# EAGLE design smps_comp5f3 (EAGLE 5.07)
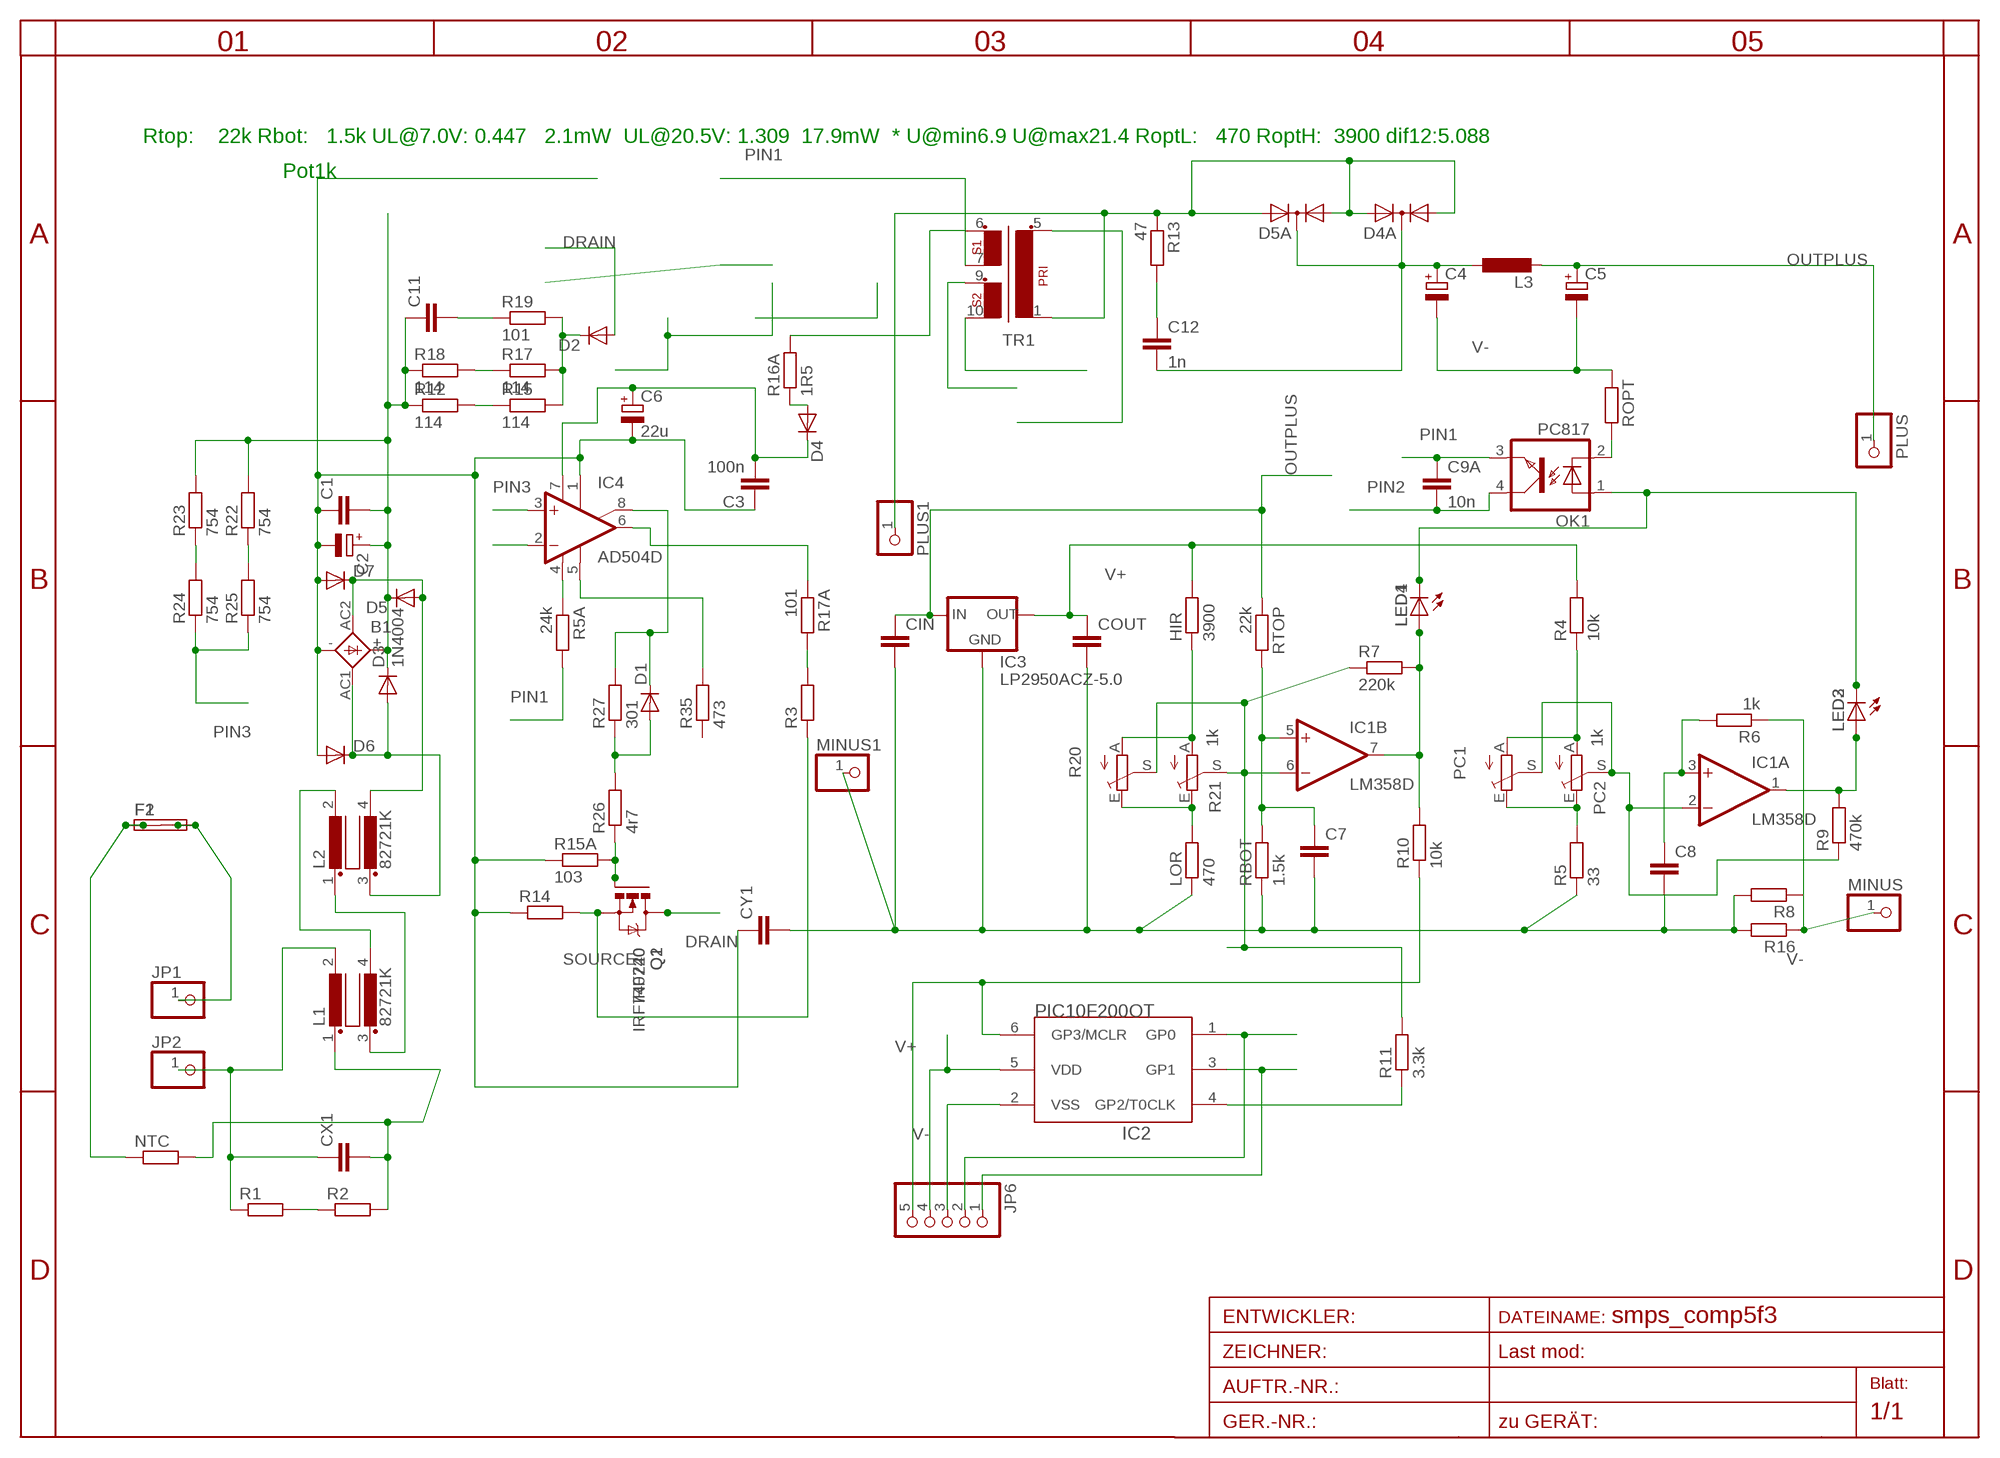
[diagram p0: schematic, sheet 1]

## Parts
B1  KBL  [KBL]
C1  C-EU050-024X044  [C050-024X044]
C2  CPOL-EUE7.5-16  [E7,5-16]
C3  100n  C-EUC0805  [C0805]
C4  CPOL-EUE5-8.5  [E5-8,5]
C5  CPOL-EUE5-8.5  [E5-8,5]
C6  22u  CPOL-EUE2.5-6  [E2,5-6]
C7  C-EUC0805  [C0805]
C8  C-EUC0805  [C0805]
C9A  10n  C-EUC0805  [C0805]
C11  C-EUC1206  [C1206]
C12  1n  C-EUC1206  [C1206]
CIN  C-EUC1206  [C1206]
COUT  C-EUC1206  [C1206]
CX1  C-EU150-084X183  [C150-084X183]
CY1  C-EU075-063X106  [C075-063X106]
D1  DIODE-MINIMELF  [MINIMELF]
D2  DIODE-C1702-15  [C1702-15]
D3  1N4004  [DO41-10]
D4  DIODE-MINIMELF  [MINIMELF]
D4A  DIODE-2AC|CAIW220V  [IW220ABS]
D5  DIODE-D-5  [D-5]
D5A  DIODE-2AC|CAIW220V  [IW220ABS]
D6  DIODE-D-5  [D-5]
D7  DIODE-D-7.5  [D-7.5]
F1  SHK20L20MM  [SHK20L]
F2  SHK20L7MM5  [7MM5]
HIR  3900  R-EU_R0805  [R0805]
IC1  LM358D  [SO08]
IC2  PIC10F200OT  [SOT23-6]
IC3  LP2950ACZ-5.0  [TO92]
IC4  AD504D  [SO08]
JP1  PINHD-1X12MM2  [1X2MM2]
JP2  PINHD-1X12MM2  [1X2MM2]
JP6  PINHD-1X5/90  [1X05/90]
L1  82721K  82721K7_5X10  [8272_7.5_10]
L2  82721K  82721K7_5  [8272_7.5]
L3  L-EU0207/12  [0207/12]
LED1  LED3MM  [LED3MM]
LED2  LED3MM  [LED3MM]
LED3  LEDCHIPLED_1206  [CHIPLED_1206]
LED4  LEDCHIPLED_1206  [CHIPLED_1206]
LOR  470  R-EU_R0805  [R0805]
MINUS  PINHD-1X12MM2  [1X2MM2]
MINUS1  PINHD-1X11X0.4  [1X01]
NTC  R-EU_0204/7  [0204/7]
OK1  PC817  [DIL04]
PC1  TRIM_EU-S64W  [S64W]
PC2  1k  TRIM_EU-CA6V  [CA6V]
PLUS  PINHD-1X12MM2  [1X2MM2]
PLUS1  PINHD-1X11X0.4  [1X01]
Q1  IRF740  IRF740X  [TO220VX]
Q2  IRF740220  [TO220BV]
R1  R-EU_R1206  [R1206]
R2  R-EU_R1206  [R1206]
R3  R-EU_0207/40  [0207/40]
R4  10k  R-EU_R0805  [R0805]
R5  33  R-EU_R1206  [R1206]
R5A  24k  R-EU_R0805  [R0805]
R6  1k  R-EU_R0805  [R0805]
R7  220k  R-EU_R0805  [R0805]
R8  R-EU_R2010  [R2010]
R9  470k  R-EU_R0805  [R0805]
R10  10k  R-EU_0207/15  [0207/15]
R11  3.3k  R-EU_0207/15  [0207/15]
R12  114  R-EU_R1206  [R1206]
R13  47  R-EU_R1206  [R1206]
R14  R-EU_0411/3V  [0411V]
R15  114  R-EU_R1206  [R1206]
R15A  103  R-EU_R1206  [R1206]
R16  R-EU_R2010  [R2010]
R16A  1R5  R-EU_R1206  [R1206]
R17  114  R-EU_R1206  [R1206]
R17A  101  R-EU_R0805  [R0805]
R18  114  R-EU_R1206  [R1206]
R19  101  R-EU_R1206  [R1206]
R20  TRIM_EU-S64W  [S64W]
R21  1k  TRIM_EU-CA6V  [CA6V]
R22  754  R-EU_R1206  [R1206]
R23  754  R-EU_R1206  [R1206]
R24  754  R-EU_R1206  [R1206]
R25  754  R-EU_R1206  [R1206]
R26  4r7  R-EU_R1206  [R1206]
R27  301  R-EU_R1206  [R1206]
R35  473  R-EU_R1206  [R1206]
RBOT  1.5k  R-EU_R0805  [R0805]
ROPT  R-EU_R0805  [R0805]
RTOP  22k  R-EU_R0805  [R0805]
TR1  EE20-2  [EE30GREEN]

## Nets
A: PC1.A PC2.A R4.1
A1: HIR.1 R20.A R21.A
AC1: F1.2A F1.2B F2.2A F2.2B JP1.1
AC2: CX1.1 JP2.1 L1.2 R1.1
CPLUS: C4.+ C12.2 D4A.C D5A.C L3.1
DRAIN: D2.A Q1.D Q2.D TR1.10
E: PC1.E PC2.E R5.2
E1: LOR.2 R20.E R21.E
F1A: F1.1A F1.1B F2.1A F2.1B NTC.1
GATE: Q1.G Q2.G R15A.2 R26.1
N$1: CX1.2 L1.1 NTC.2 R2.2
N$3: L1.4 L2.2
N$4: B1.AC1(AC2) D3.A D6.C L2.3
N$5: L1.3 L2.1
N$6: R1.2 R2.1
N$7: C8.1 IC1.3(A:+IN) R6.2
N$10: IC1.6(B:-IN) R7.1 R11.2 R20.S R21.S
N$11: IC1.1(A:OUT) LED2.A LED3.A R9.2
N$12: OK1.2(C) ROPT.2
N$13: LED1.K(C) LED2.K(C) LED3.C LED4.C OK1.1(A)
N$15: IC2.6(GP3/MCLR) JP6.5 R10.1
N$16: C7.1 IC1.5(B:+IN) RBOT.2 RTOP.2
N$17: IC2.1(GP0) JP6.2
N$18: IC2.3(GP1) JP6.1
N$19: IC2.4(GP2/T0CLK) R11.1
N$20: B1.AC2(AC1) D5.A D7.C L2.4
N$23: C11.2 R19.1
N$24: D2.C R15.2 R17.2 R19.2
N$25: D1.A R26.2 R27.1
N$26: R17.1 R18.2
N$27: C12.1 R13.2
N$28: R12.2 R15.1
N$29: R22.1 R25.2
N$30: IC4.4(V-) R5A.1
N$31: R23.1 R24.2
N$32: IC4.6(OUT) R17A.1
N$33: D1.C IC4.8(ON2) R27.2
N$34: R3.2 R17A.2
OUT: MINUS.1 R6.1 R8.1 R16.1
OUTB: IC1.7(B:OUT) LED1.A LED4.A R7.2 R10.2
OUTPLUS: C5.+ CIN.1 IC3.3(IN) L3.2 PLUS.1 RTOP.1
PIN1: B1.- C1.1 C2.- C3.1 C6.- C9A.1 CY1.1 D6.A D7.A IC4.1(ON1) OK1.3(EMIT) R5A.2 R14.1 R15A.1 TR1.9
PIN2: C9A.2 IC4.2(-IN) OK1.4(COL)
PIN3: IC4.3(+IN) R24.1 R25.1
PIN5: IC4.5(OPT) R35.2
PIN7: C3.2 C6.+ D4.C IC4.7(V+)
PLUS: B1.+ C1.2 C2.+ C11.1 D3.C D5.C R12.1 R18.1 R22.2 R23.2 TR1.7
S: IC1.2(A:-IN) PC1.S PC2.S R9.1
SOURCE: Q1.S Q2.S R3.1 R14.2
TPLUS: D4A.A1 D4A.A2 D5A.A1 D5A.A2 PLUS1.1 R13.1 TR1.1
V+: COUT.1 HIR.2 IC2.5(VDD) IC3.1(OUT) JP6.4 R4.2
V-: C4.- C5.- C7.2 C8.2 CIN.2 COUT.2 CY1.2 IC2.2(VSS) IC3.2(GND) JP6.3 LOR.1 MINUS1.1 R5.1 R8.2 R16.2 RBOT.1 ROPT.1 TR1.5
X: R16A.2 TR1.6
Y: D4.A R16A.1
Unconnected: R35.1

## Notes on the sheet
- Rtop:    22k Rbot:   1.5k UL@7.0V: 0.447   2.1mW  UL@20.5V: 1.309  17.9mW  * U@min6.9 U@max21.4 RoptL:   470 RoptH:  3900 dif12:5.088
- Pot1k

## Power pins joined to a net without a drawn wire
V+: IC1.8(P:V+)
V-: IC1.4(P:V-)

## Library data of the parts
B1 = rectifier:KBL: DIOTEC RECTIFIER
C1 C3 C7 C8 C9A C11 C12 CIN COUT CX1 CY1 = rcl:C-EU: CAPACITOR, European symbol
C2 C4-C6 = rcl:CPOL-EU: POLARIZED CAPACITOR, European symbol
D1 D2 D4-D7 = diode:DIODE-: DIODE
D3 = diode:1N4004: DIODE
D4A D5A = diode:DIODE-2AC|CA: Dual DIODE Anode-Cathode|Cathode-Anode
F1 F2 = fuse:SHK20L: FUSE HOLDER 5 x 20 mm, SH contact, SHH1 Schukat, E1073 Buerklin
HIR LOR NTC R1 R2 R4 R5 R5A R6-R15 R15A R16 R16A R17 R17A R18 R19 R22-R27 R35 RBOT ROPT RTOP = rcl:R-EU_: RESISTOR, European symbol
IC1 = linear:LM358: OP AMP also LM158; LM258; LM2904 Source: http://cache.national.com/ds/LM/LM158.pdf
IC2 = microchip-5:PIC10F20*: uPC nW 0,25/0,5k Program Flash memory
IC3 = v-reg:LP2950?*: Source: http://cache.national.com/ds/LP/LP2950.pdf
IC4 = linear:AD504: OP AMP
JP1 JP2 MINUS MINUS1 PLUS PLUS1 = pinhead:PINHD-1X1: PIN HEADER
JP6 = pinhead:PINHD-1X5: PIN HEADER
L1 L2 = inductors:82721K: FILTER
L3 = rcl:L-EU: INDUCTOR, European symbol
LED1-LED4 = led:LED: LED
OK1 = optocoupler:PC817: SHARP OPTO COUPLER
PC1 PC2 R20 R21 = pot:TRIM_EU-: POTENTIOMETER
Q1 Q2 = transistor-power:IRF740: N-CHANNEL MOS FET
R3 = rcl-2:R-EU_: RESISTOR, European symbol
TR1 = trafo:EE20-2: TRANSFORMER 1 primary winding, 2 secondary windings ERA

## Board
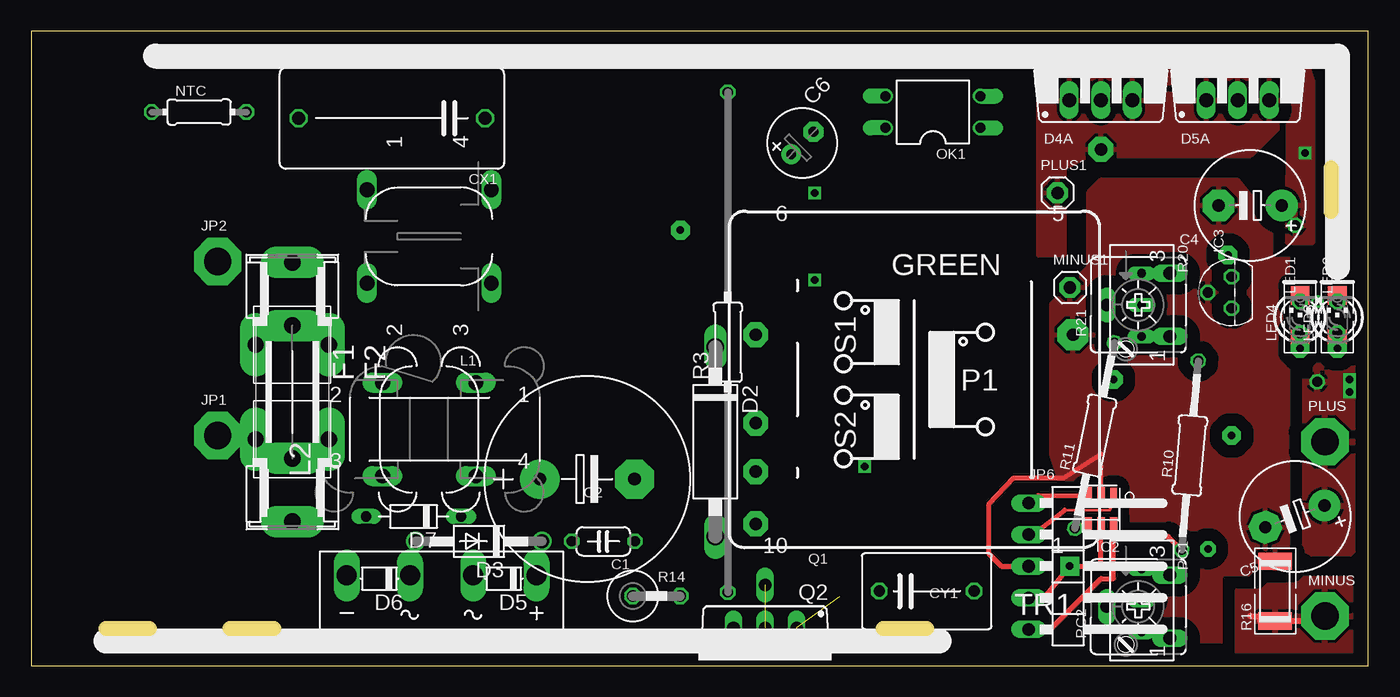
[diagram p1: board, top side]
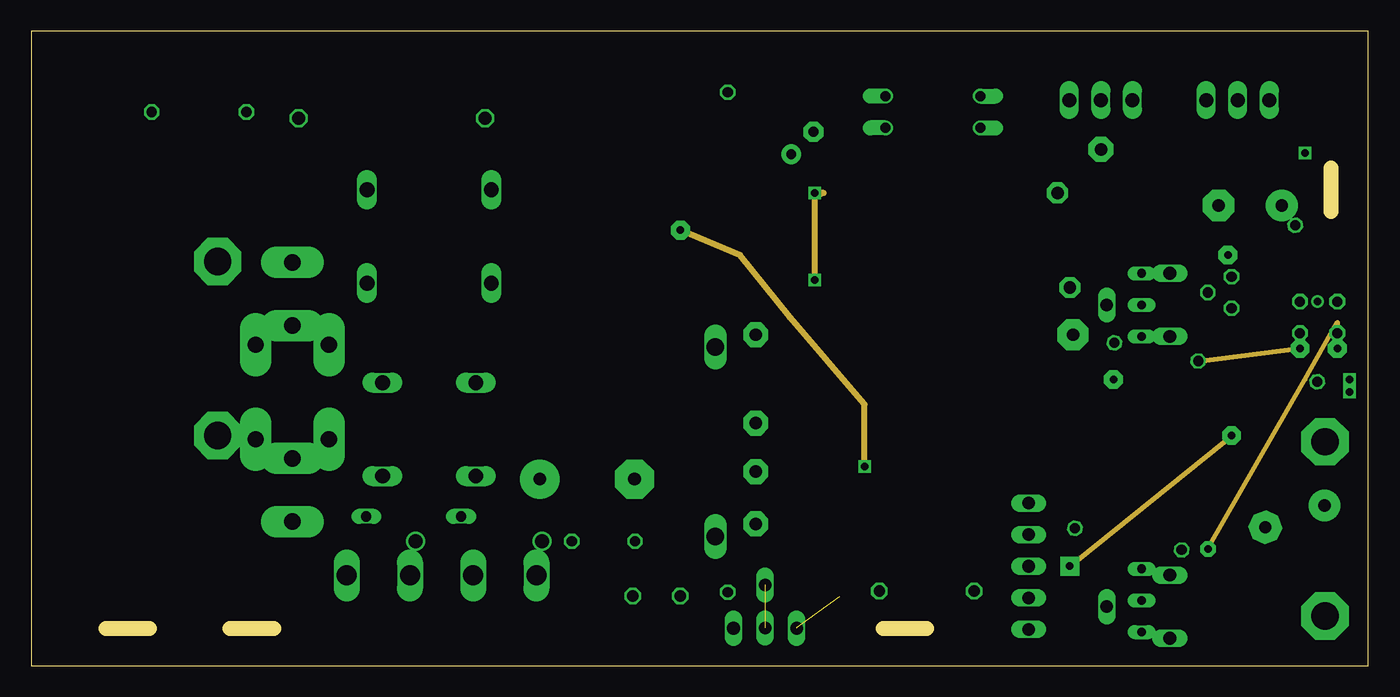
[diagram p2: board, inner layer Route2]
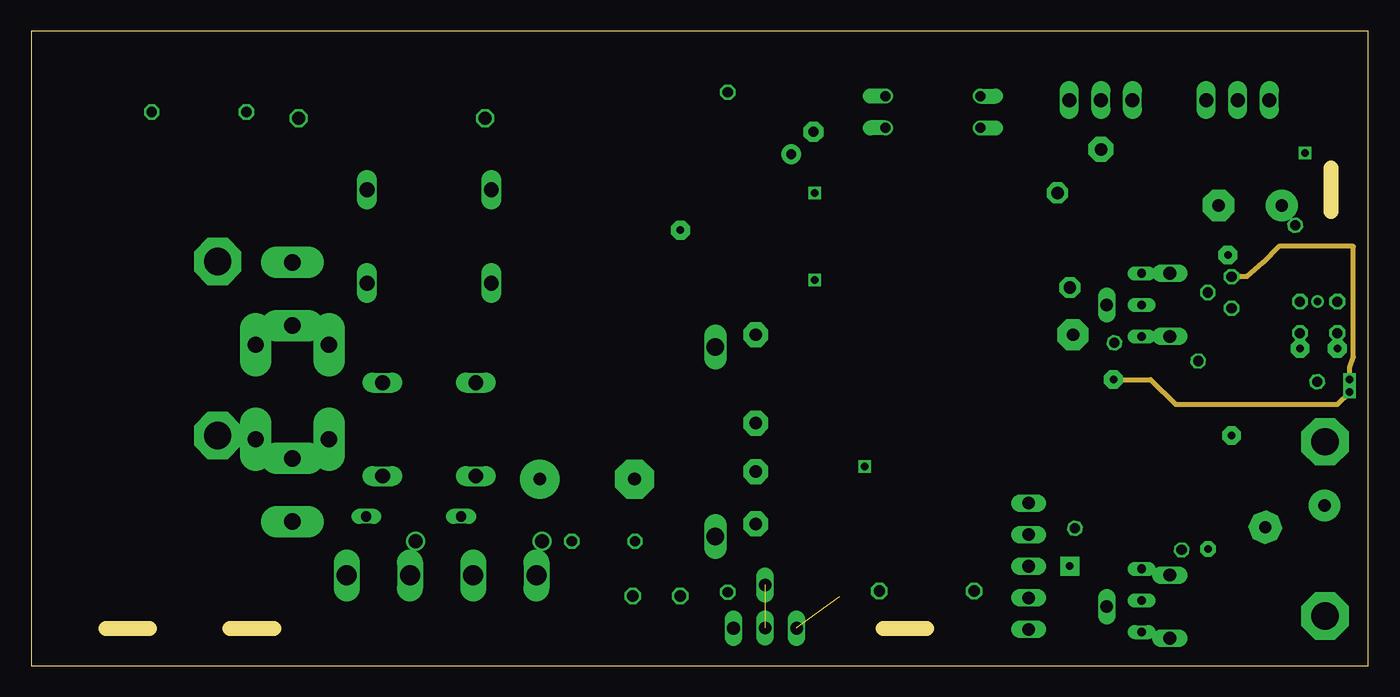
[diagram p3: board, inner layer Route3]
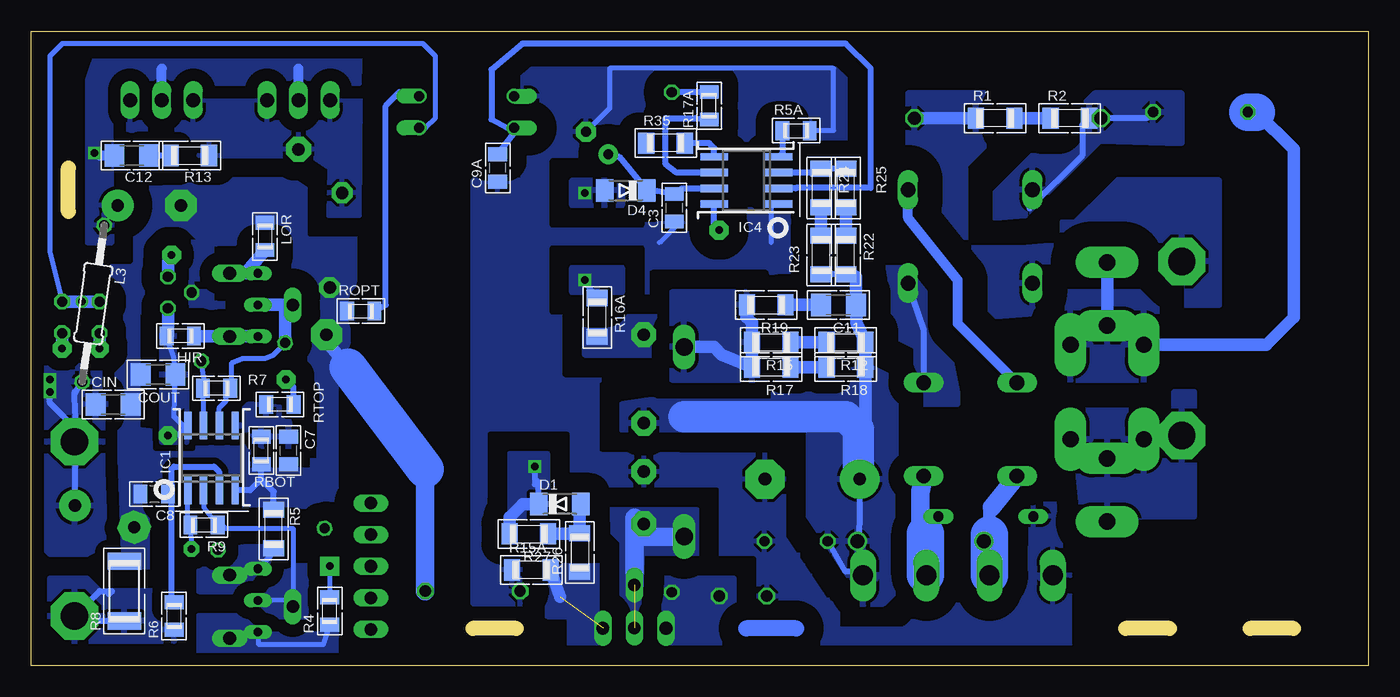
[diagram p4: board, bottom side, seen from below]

Size 107.5 x 51 mm. Coordinates in mm from the lower left corner, seen from the top.
Outline: 0,0 107.5,0 107.5,51 0,51 0,0
Copper layers (1*16): Top 0.035mm / dielectric 1.5mm / Bottom 0.035mm
Design rules "default *": minimum track width 10mil, minimum drill 20mil, track to track 8mil, track to pad 8mil, pad to pad 8mil, via to via 8mil, smd to smd 8mil, copper to edge 40mil, drill to drill 8mil, minimum pad ring 8mil, minimum via ring 8mil, stop-mask expansion 4mil, vias tented up to drill 0mil, thermal gap 10mil
Milling: 4 lines

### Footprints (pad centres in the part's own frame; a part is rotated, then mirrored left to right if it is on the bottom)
KBL = drill 1.6 long: + -7.62,-1.27; - 7.62,-1.27; AC1 2.54,-1.27; AC2 -2.54,-1.27
C050-024X044 = drill 0.813 octagon: 1 -2.54,0; 2 2.54,0
E7,5-16 = drill 1.016 pad 3.15 round: + -3.81,0 | drill 1.016 pad 3.15 octagon: - 3.81,0
C0805 = smd 1.1 x 1.5: 1 -1.1,0; 2 1.1,0
E5-8,5 = drill 1 pad 2.54 round: + -2.54,0 | drill 1 pad 2.54 octagon: - 2.54,0
E2,5-6 = drill 0.8 pad 1.6 round: + -1.27,0 | drill 0.8 pad 1.6 octagon: - 1.27,0
C1206 = smd 1.6 x 1.8: 1 -1.4,0; 2 1.4,0
C150-084X183 = drill 1.016 octagon: 1 -7.493,0; 2 7.493,0
C075-063X106 = drill 0.914 octagon: 1 -3.81,0; 2 3.81,0
MINIMELF = smd 1.4 x 1.8: A 1.7,0; C -1.7,0
C1702-15 = drill 1.397 long: A 7.62,0; C -7.62,0
DO41-10 = drill 1.118 round: A 5.08,0; C -5.08,0
IW220ABS = drill 1.118 long: A1 -2.54,-2.54; A2 2.54,-2.54; C 0,-2.54
D-5 = drill 0.813 octagon: A 2.54,0; C -2.54,0
D-7.5 = drill 0.813 long: A 3.81,0; C -3.81,0
SHK20L = drill 1.321 pad 2.54 long: 1A -10.414,0; 1B -5.334,0; 2A 10.414,0; 2B 5.334,0
7MM5 = drill 1.3 pad 2.54 long: 1A -3.8,2.94; 1B -3.8,-2.94; 2A 3.8,2.94; 2B 3.8,-2.94
R0805 = smd 1.1 x 1.5: 1 -1.1,0; 2 1.1,0
SO08 = smd 0.6 x 2.2: 1 -1.905,-2.6; 2 -0.635,-2.6; 3 0.635,-2.6; 4 1.905,-2.6; 5 1.905,2.6; 6 0.635,2.6; 7 -0.635,2.6; 8 -1.905,2.6
SOT23-6 = smd 0.55 x 1.2: 1 -1.016,-1.2 | smd 0.6 x 1.27: 2 0,-1.2; 3 1.016,-1.2; 4 1.016,1.2; 5 0,1.2; 6 -1.016,1.2
TO92 = drill 0.813 octagon: 1 -1.27,0; 2 0,1.905; 3 1.27,0
1X2MM2 = drill 2.2 pad 3.81 octagon: 1 0,0
1X05/90 = drill 1.016 long: 1 -5.08,-3.81; 2 -2.54,-3.81; 3 0,-3.81; 4 2.54,-3.81; 5 5.08,-3.81
8272_7.5_10 = drill 1.194 long: 1 3.75,5; 2 -3.75,5; 3 -3.75,-5; 4 3.75,-5
8272_7.5 = drill 1.194 long: 1 3.75,3.75; 2 -3.75,3.75; 3 -3.75,-3.75; 4 3.75,-3.75
0207/12 = drill 0.813 octagon: 1 -6.35,0; 2 6.35,0
LED3MM = drill 0.8 pad 1.27 octagon: A -1.27,0; K 1.27,0
CHIPLED_1206 = smd 1.5 x 1.5: A 0,-1.75; C 0,1.75
1X01 = drill 1 pad 1.676 octagon: 1 0,0
0204/7 = drill 0.813 octagon: 1 -3.81,0; 2 3.81,0
DIL04 = drill 0.813 offset: 1 -1.27,-3.81; 2 1.27,-3.81; 3 1.27,3.81; 4 -1.27,3.81
S64W = drill 0.7 long: A 2.54,1.27; E -2.54,1.27; S 0,1.27
CA6V = drill 1.016 long: A -2.54,-2.54; E 2.54,-2.54; S 0,2.54
TO220VX = drill 1.016 long: D 0,-3.5; G -2.54,0; S 2.54,0
TO220BV = drill 1.016 long: D 0,-2.54; G -2.54,-2.54; S 2.54,-2.54
R1206 = smd 1.3 x 1.7: 1 -1.55,0; 2 1.55,0
0207/40 = drill 0.813 octagon: 1 -20.08,0; 2 20.08,0
R2010 = smd 1.4 x 2.7: 1 -2.4,0; 2 2.4,0
0207/15 = drill 0.813 octagon: 1 -7.62,0; 2 7.62,0
0411V = drill 0.914 octagon: 1 -2.54,0; 2 1.27,0
EE30GREEN = drill 1 pad 2 octagon: 1 15,18.5; 6 -12.75,3.6; 7 -12.75,-3.5; 9 -12.75,-7.4; 10 -12.75,-11.6 | drill 1 pad 2.5 octagon: 5 12.75,3.6

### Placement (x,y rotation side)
B1  33,6 180 top
C1  46,10 180 top
C2  44.7,15 0 top
C3  55.8,36.8 90 bottom
C4  98,37 180 top
C5  101.6,12 200 top
C6  62,42 45 top
C7  86.8,17.3 270 bottom
C8  97.6,13.8 180 bottom
C9A  70,40 90 bottom
C11  42.6,29 180 bottom
C12  99.4,41 180 bottom
CIN  100.9,21 0 bottom
COUT  97.3,23.4 180 bottom
CX1  29,44 180 top
CY1  72,6 0 top
D1  65,13 0 bottom
D2  55,18 270 top
D3  36,10 180 top
D4  59.7,38.2 180 bottom
D4A  86,48 0 top
D5  38,7 180 top
D5A  97,48 0 top
D6  28,7 180 top
D7  30.75,12 180 top
F1  21,22 270 top
F2  21,22 270 top
HIR  95.5,26.5 180 bottom
IC1  93,16.7 0 bottom
IC2  86,12.5 180 top
IC3  96.5,30 90 top
IC4  50,39 90 bottom
JP1  15,18.5 0 top
JP2  15,32.5 0 top
JP6  84,8 270 top
L1  32,34.5 90 top
L2  32,19 0 top
L3  102.5,29.1 262 bottom
LED1  102,28 90 top
LED2  105,28 90 top
LED3  105,28 0 top
LED4  102,28 0 top
LOR  88.7,34.5 270 bottom
MINUS  104,4 0 top
MINUS1  83.5,30.4 0 top
NTC  13.5,44.5 0 top
OK1  72.5,44.5 90 top
PC1  88,5.25 270 top
PC2  89,4.75 90 top
PLUS  104,18 0 top
PLUS1  82.5,38 0 top
Q1  59,3 180 top
Q2  59,0.5 180 top
R1  30,44 0 bottom
R2  24,44 0 bottom
R3  56,26 90 top
R4  83.5,4.4 90 bottom
R5  88,11 270 bottom
R5A  46,43 0 bottom
R6  96,4 90 bottom
R7  92.6,22.3 180 bottom
R8  100,6 90 bottom
R9  93.6,11.3 180 bottom
R10  93.15,16.9 85 top
R11  85.5,18.5 78 top
R12  42,26 180 bottom
R13  94.75,41 180 bottom
R14  50.9,5.6 0 top
R15  48,26 180 bottom
R15A  67.3,7.7 0 bottom
R16  100,6 90 top
R16A  62,28 270 bottom
R17  48,24 180 bottom
R17A  53,45 90 bottom
R18  42,24 180 bottom
R19  48.4,29 180 bottom
R20  88,29 270 top
R21  89,29 90 top
R22  42,33 270 bottom
R23  44,33 270 bottom
R24  44,38.4 270 bottom
R25  42,38.4 270 bottom
R26  63.4,9.1 90 bottom
R27  67.5,10.6 180 bottom
R35  56.5,42 0 bottom
RBOT  89,17.3 90 bottom
ROPT  81,28.5 0 bottom
RTOP  87.5,21 180 bottom
TR1  71,23 0 top

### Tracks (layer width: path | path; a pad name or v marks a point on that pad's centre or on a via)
A
  Bottom 0.4: R4.1 84.01,1.7 89.2,1.7 89.2,2.71 PC1.A
  Bottom 0.5: PC1.A PC2.A
  pour Bottom (isolate 1, rank 2, no thermals): 83,4 94,4 94,1 83,1
A1
  Bottom 0.5: R21.A 92.46,26.5
  Bottom 1: R20.A R21.A | 92.46,26.5 HIR.1
AC1
  Bottom 0.5: F1.2B 22.41,16.67 F2.2A
  pour Bottom (isolate 2, rank 3): 14,22 24,22 23,12 14,12
AC2
  Bottom 1: R1.1 CX1.1
  pour Bottom (isolate 2, rank 3): 30,46 37,46 37,40 31,28 18,29 12,29 12,39 30,39
CPLUS  (via drill 0.6)
  Bottom 0.813: D4A.C 86,48 | D5A.C 97,48 | C12.2 102,41
  other vias: 102.4,41.2
  pour Bottom (isolate 1): 81,50 102,50 103,47 103,34 101,34 101,37 101.1,46.8 81.1,46.8
  pour Top (isolate 1): 81,50 102,50 103,47 103,34 101,34 101,37 101.1,46.8 81.1,46.8
DRAIN  (1 unrouted)
  Bottom 1.5: 59,11 Q1.D | 59,11 59,11.89 TR1.10 | D2.A 58.38,10.38 59,11
  pour Bottom (isolate 1.6, rank 2, no thermals): 54,12.5 61,12.5 61,11 60,10 60,3 58,3 58,8 54,8
E
  Bottom 0.406: R5.2 88.27,8.8 PC1.E PC2.E
  pour Bottom (isolate 1, rank 2, no thermals): 90,7 89,7 87,10 94,9 94,6 91,6
E1
  Bottom 0.406: 90.27,31.6 R20.E
  Bottom 1: R20.E R21.E | LOR.2 90.27,31.6
F1A
  Bottom 0.5: F1.1B 22.41,27.33
  Bottom 1: 9,44.5 6,41.5 6,28 8.2,25.8 F2.1B 19.59,27.33 F1.1B F1.1A | 22.41,27.33 F2.1A
  Bottom 3: 9,44.5 NTC.1
  pour Bottom (isolate 2): 17,26 17,30 25,30 25,23 17,23
GATE  (2 unrouted)
  Bottom 1: 64.99,5.54 R15A.2
  pour Bottom (isolate 1.6, rank 3, no thermals): 61,8 66,8 66,4 64.2,4 64.2,1 61,1
N$1
  Bottom 0.5: 21.51,43.74 CX1.2 17.81,44 NTC.2 | L1.1 27.25,36.75 23,41 23,43.45 R2.2
  Bottom 1: CX1.2 R2.2
  pour Bottom (isolate 2, rank 2): 15,46 22,46 30,38 30,36 27.6,36.2 21.6,42.2 15,42
N$2
  Bottom 1.27: 46,3 50,3
N$3
  Bottom 0.5: 36.75,37.75 L1.4
  Bottom 0.813: 36.75,37.75 37,37.75 37,36 33,31 33,27.5 L2.2
N$4
  Bottom 0.5: D6.C 30.54,7.19 B1.AC1 | 30.46,12.54 30.25,12.75
  Bottom 1: 30.46,10.54 30.46,12.54
  Bottom 1.5: 30.25,12.75 L2.3 | 30.46,10 D3.A
  Bottom 3: B1.AC1 30.46,10 30.46,10.54
N$5
  Bottom 0.5: L2.1 35.75,27 L1.3
  pour Bottom (isolate 2, rank 6, no thermals): 33,22 35,32 40,32 40,21 33,21
N$6
  Bottom 1: R2.1 R1.2
N$7
  Bottom 0.5: R6.2 96.2,5 96.2,14.65 | 96.2,14.65 C8.1 | 96.2,14.65 96.2,15.8 96,16 92.8,16 92.4,15.6 92.4,14.13 IC1.3
N$10
  Bottom 0.4: 91.36,24.34 90.5,24.7 88.7,24.7
  Bottom 0.406: 87.08,29 R21.S | R11.2 87.08,25.92 88,25 88.7,24.7 | IC1.6 92.36,20.73 91.8,21.3 91.8,22 R7.1 91.36,22.43 91.36,24.34
  Bottom 1: R21.S R20.S | R11.2 87.08,29
N$11  (via drill 0.6 pad 1.25, 0.6 pad 1.5)
  Top 0.5: v105,25.5 LED3.A
  Route2 0.406: v94.6,9.4 102.4,23 105,27.6 v105,25.5
  Bottom 0.4: 94.6,10.1 R9.2 94.91,11.2 IC1.1
  Bottom 0.406: v94.6,9.4 94.6,10.1
  Bottom 1: v105,25.5 LED2.A
N$12
  Bottom 0.5: ROPT.2 79,29 79,45 77.9,46.1 76.64,46.1 OK1.2
N$13  (via drill 0.6)
  Top 0.5: LED2.K LED3.C | LED1.K LED4.C
  Bottom 0.4: OK1.1 75.77,43.23 75,44 75,49 76,50 105,50 106,49 106,33.27 LED2.K
  Bottom 1: LED1.K v103.4,29.27 LED2.K
N$15
  Top 0.406: IC2.6 87,10.8 87,10.4 | JP6.5 81.92,2.92 86,7 87,7 87,10.4 | R10.1 91.42,10.38 87,10.4
N$16
  pour Bottom (isolate 0.406, rank 2): 87.1,20.7 90,21 91,20 91,19 90,19 89,17.7 86.1,17.7
N$17
  Top 0.2: 83.1,12.5 86.7,12.5
  Top 0.254: 86.7,12.5 87,13.18
  Top 0.406: 87.2,13.2 IC2.1 87,13.18 | JP6.2 80.54,10.54 83.1,12.5
N$18
  Top 0.406: JP6.1 80.96,13.68 IC2.3
N$19
  Top 0.406: IC2.4 84.1,11.3 R11.1
N$20
  Bottom 0.5: D5.A 35.46,7.19 B1.AC2
  Bottom 1: D7.C 35,12 36,11
  Bottom 1.5: B1.AC2 35.6,7.33 | L2.4 36,14 36,11 35.6,10.6 35.08,11.12
  Bottom 3: 35.6,7.33 35.6,10.6
N$23
  Bottom 1: C11.2 R19.1
N$24
  Bottom 1: D2.C 52.62,25.62 52,25 R17.2 R15.2 49.55,27.55 50,28 50,28.95 R19.2
  pour Bottom (isolate 1, rank 3): 50,30 56,30 56,23 49,23
N$25
  Bottom 1: R27.1 63.45,10.6 R26.2 63.4,12.9 D1.A
N$26
  Bottom 1: R18.2 R17.1
N$27
  Bottom 0.5: R13.2 C12.1
N$28
  Bottom 1: R12.2 R15.1
N$29
  Bottom 1: R22.1 R25.2
N$30
  Bottom 0.5: R5A.1 47.1,41.2 IC4.4
N$31
  Bottom 1: R23.1 R24.2
N$32
  Bottom 0.5: IC4.6 55.63,39.63 56.5,40.3 56.5,44 54.1,44 R17A.1
N$33  (via drill 0.6, 0.6 pad 1.5)
  Route2 0.5: v52.2,35 57,33 61,28 67,21 v67,16
  Bottom 0.5: IC4.8 52.6,35.4 v52.2,35 | 67,15 v67,16 | D1.C 66.7,14.7 67,15 | 67,15 67,14.55
  Bottom 1: R27.2 69.05,11.95 68,13 D1.C
  pour Bottom (isolate 1, rank 2): 66,17 69,17 69,12 66,12 66,16
N$34
  Bottom 0.5: R3.2 54.02,46.08 R17A.2
OUT
  Top 0.5: R16.1 103.6,3.6 MINUS.1 | R16.1 98.8,3.6 | 98,4 99.6,4 R16.1
  Bottom 0.5: 101.25,5.75 101,6 102,6 MINUS.1 103.6,3.6 R16.1
  pour Bottom (isolate 1.016, rank 3): 102,6 103,7 106,7 106,2 96,2 97,6
  pour Top (isolate 1.016, rank 3): 100,7 106,7 106,1 97,1 97,6 99,6
OUTB  (via drill 0.6 pad 1.5)
  Top 0.5: v102,25.5 LED4.A
  Route2 0.406: R10.2 v102,25.5
  Bottom 0.4: R7.2 93.6,22.6
  Bottom 0.406: IC1.7 93.64,21.07 R7.2 | 93.6,22.6 93.6,23.04 R10.2
  Bottom 1: v102,25.5 LED1.A
OUTPLUS  (via drill 0.6, 0.6 pad 1.5)
  Route3 0.406: v87,23 90,23 92,21 105,21 v106,22 | IC3.3 97.73,31.27 99,32.4 100.3,33.7 106.3,33.7 106.3,24.8 106,24 v106,23
  Bottom 0.5: L3.2 103.95,21.95 104,22 104,21.54 103.88,19.01 | C5.+ 103.88,19.01 | RTOP.1 86.4,22.4 v87,23 | v106,23 106,21.13 103.88,19.01
  Bottom 1: IC3.3 96.5,32.5 v96.2,33
  pour Bottom (isolate 1, rank 5): 107,28 107,10 106,9 103,9 101,10 101,28
  pour Top (isolate 1, rank 5): 107,28 107,10 106,9 103,9 101,10 101,28
PIN1
  Bottom 0.406: B1.- 25,7.27 | IC4.1 48,37.09 48,34 | C3.1 55.4,35.6 57,34 | R5A.2 43,43 43,48 61,48 61,44.8 C6.-
  pour Bottom (isolate 1.6, rank 5): 40,50 68,50 68,39 72,39 72,5 66,5 66,1 61,1 61,8 50,8 50,5 47,5 47,1 24,1 24,13 29,13 29,9 42,9 42,10 45,13 45,16 40,21
PIN2
  Bottom 0.5: C9A.2 68.51,43.05 OK1.4 69.23,43.23 70.5,43.9 70.5,47.9 68,50 42,50 40,48 40,38.4 46,38.4 46.03,38.37 IC4.2
PIN3
  Bottom 0.5: IC4.3 44.31,39.63 R24.1 R25.1
PIN5
  Bottom 0.5: IC4.5 52.6,41.6 53,42 R35.2
PIN7
  Bottom 0.5: IC4.7 55.19,38.37 C3.2 57.15,38.15 D4.C 60.2,40.9 60.63,40.9 C6.+
PLUS
  Bottom 0.5: R22.2 R23.2 | 40.92,7.57 C2.+ | B1.+ 40.92,7.57 | 40.92,7.57 42.03,7.57 C1.2
  Bottom 1: 41,19 40.45,19.55 R18.1 R12.1 41.15,27.55 C11.1 41.2,31.25 R22.2 | D5.C 40.54,7.19 B1.+
  Bottom 2.54: 55,20 42,20 41,19 41,15.08 C2.+
  pour Bottom (isolate 1.27, rank 4): 40,24 60,21 60,19 45,19 45,12 41,6 41,5 39,5 38,6 38,23
S
  Bottom 0.4: IC1.2 93.6,13.4 93.6,12.7 R9.1
  Bottom 0.406: 86.4,5 86.4,11 92,11 92,11.2 R9.1 | 86.96,5.25 PC1.S
  Bottom 0.5: PC2.S 86.71,5 | 86.71,5 86.4,5 | 86.71,5 86.96,5.25
  pour Bottom (isolate 1, no thermals): 85,8 87,8 89,5 88,4 85,4
SOURCE
  pour Bottom (isolate 1.6, no thermals): 51,7 57,7 57,1 52,1 51,2
TPLUS
  pour Bottom (isolate 1.016, rank 2): 81.1,36.2 81,46 82,47 100,47 101,46 101,42.3 94,42.3 94,41 85,41 83.5,40 83.6,36.2
  pour Top (isolate 0.5, rank 2): 81,33 81,46 82,47 100,47 101,46 101,44 98,41 85,41 83,40 83,33
V+  (via drill 0.6 pad 1.5)
  Top 0.406: IC2.5 86,8 v83.5,8 81.46,5.46 JP6.4
  Route2 0.406: v83.5,8 v96.5,18.5
  Bottom 0.4: HIR.2 96,24.7 COUT.1 96,20 95,19 95,18.7 IC1.8 95.6,18.6 | v83.5,8 R4.2
  Bottom 0.5: HIR.2 96.5,26.6 | 95.6,18.6 96.9,18.6 v96.5,18.5
  Bottom 1: 96.5,26.6 IC3.1
  pour Bottom (isolate 0.406, rank 2): 96,27 97,27 97,18 95,18 95,22 95,24 96,25
V-
  Top 0.406: IC2.2 86,16 | JP6.3 78,8 77,9 77,13 79,15.1 83,15.1 86,17
  Bottom 0.5: IC1.4 89.9,14.1 89,15 | 89,15 RBOT.1 | R5.1 88,14 89,15
  Bottom 1: 82,24 83.7,26
  Bottom 1.5: CY1.2 75.81,15.81
  Bottom 3: 75.81,15.81 82,24
  pour Bottom (isolate 1.5, rank 4, no thermals): 97,40 86,40 81.5,37 81.5,31 82,29 82,26 83,23 83,6 100,8 101,34
  pour Top (isolate 1, rank 4): 97,39 86,39 85,38 85,32 82,29 82,17 85,8 86,2 101,2 101,34
  pour Bottom (isolate 1, rank 4): 93,34 95,34 95,29 93,29
  pour Bottom (isolate 0.5, rank 4): 90,18 99,19 99,15 90,15
X
  pour Bottom (isolate 1.676, rank 2, no thermals): 58,28 63,28 63,25 57,25 57,28
Y  (via drill 0.6)
  Route2 0.5: v63,31 63,37.7 63.7,38 v63,38
  Bottom 0.5: R16A.1 v63,31
  pour Bottom (isolate 1, rank 2): 64,32 60,32 60,30 64,30
  pour Bottom (isolate 1, rank 2): 64,39 60,39 60,37 64,37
